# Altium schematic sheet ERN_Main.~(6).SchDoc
size A; SheetNumber: 1; SheetTotal: 1; SPICEModelCacheDBTNACQE: <root> / <DocumentId>DBTNACQE</DocumentId> / <CacheFrame Number="0"> / <Model Name="1n5400" Kind="MDL"> / <Text>*1N5400 MCE / * 50V 3A Si Rectifier pkg:DO-201 1,2 / .MODEL 1N5400 D(IS=2.68E-12 RS=0.00977 N=1.17 TT=1.44E-5 CJO=1.24E-10 / + VJ=0.6 M=0.333 BV=66.6 IBV=1E-5 )</Text> / </Model> / <Model Name="led2" Kind="MDL"> / <Text>*Typ RED,GREEN,YELLOW,AMBER GaAs LED: Vf=2.1V Vr=4V If=40mA trr=3uS / *LED Pinout: 1=A, 2=K / .MODEL LED2 D (IS=93.1P RS=42M N=4.61 BV=4 IBV=10U / + CJO=2.97P VJ=.75 M=.333 TT=4.32U)</Text> / </Model> / </CacheFrame> / </root>
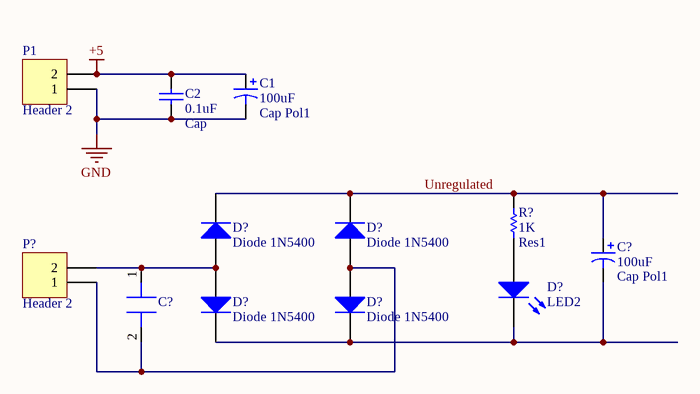
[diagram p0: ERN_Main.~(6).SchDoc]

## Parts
(Parts that share a designator on the sheet are numbered #1, #2 ... from top to bottom, then left to right.)
C1  Cap Pol1  value 100uF  [RB7.6-15]
C2  Cap  value 0.1uF  [RAD-0.3]
C?#1  Cap Pol1  value 100uF  [RB7.6-15]
C?#2  C2220C944K5GLCAUTO  [CAPC5750X39M]  (value not drawn)
D?#1  Diode 1N5400  [DO-201AD]
D?#2  Diode 1N5400  [DO-201AD]
D?#3  LED2  [3.2X1.6X1.1]
D?#4  Diode 1N5400  [DO-201AD]
D?#5  Diode 1N5400  [DO-201AD]
P1  Header 2  [HDR1X2]
P?  Header 2  [HDR1X2]
R?  Res1  value 1K  [AXIAL-0.3]

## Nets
+5: C1.1 C2.2 P1.2
GND: C1.2 C2.1 P1.1
Unregulated: C?#1.1 D?#1.2(K) D?#2.2(K) R?.2
NetC?#1_2: C?#1.2 D?#3.2(K) D?#4.2(K) D?#5.2(K)
NetC?#2_1: C?#2.1 D?#1.1(A) D?#4.1(A) P?.2
NetC?#2_2: C?#2.2 D?#2.1(A) D?#5.1(A) P?.1
NetD?#3_1: D?#3.1(A) R?.1

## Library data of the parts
C1 C?#1 = Cap Pol1: Polarized Capacitor (Radial)
C2 = Cap: Capacitor
C?#2 = C2220C944K5GLCAUTO: CAP CER 0.94UF 50V C0G/NP0 2220
D?#1 D?#2 D?#4 D?#5 = Diode 1N5400: 3 Amp General Purpose Rectifier
D?#3 = LED2: Typical RED, GREEN, YELLOW, AMBER GaAs LED
P1 P? = Header 2: Header, 2-Pin
R? = Res1: Resistor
